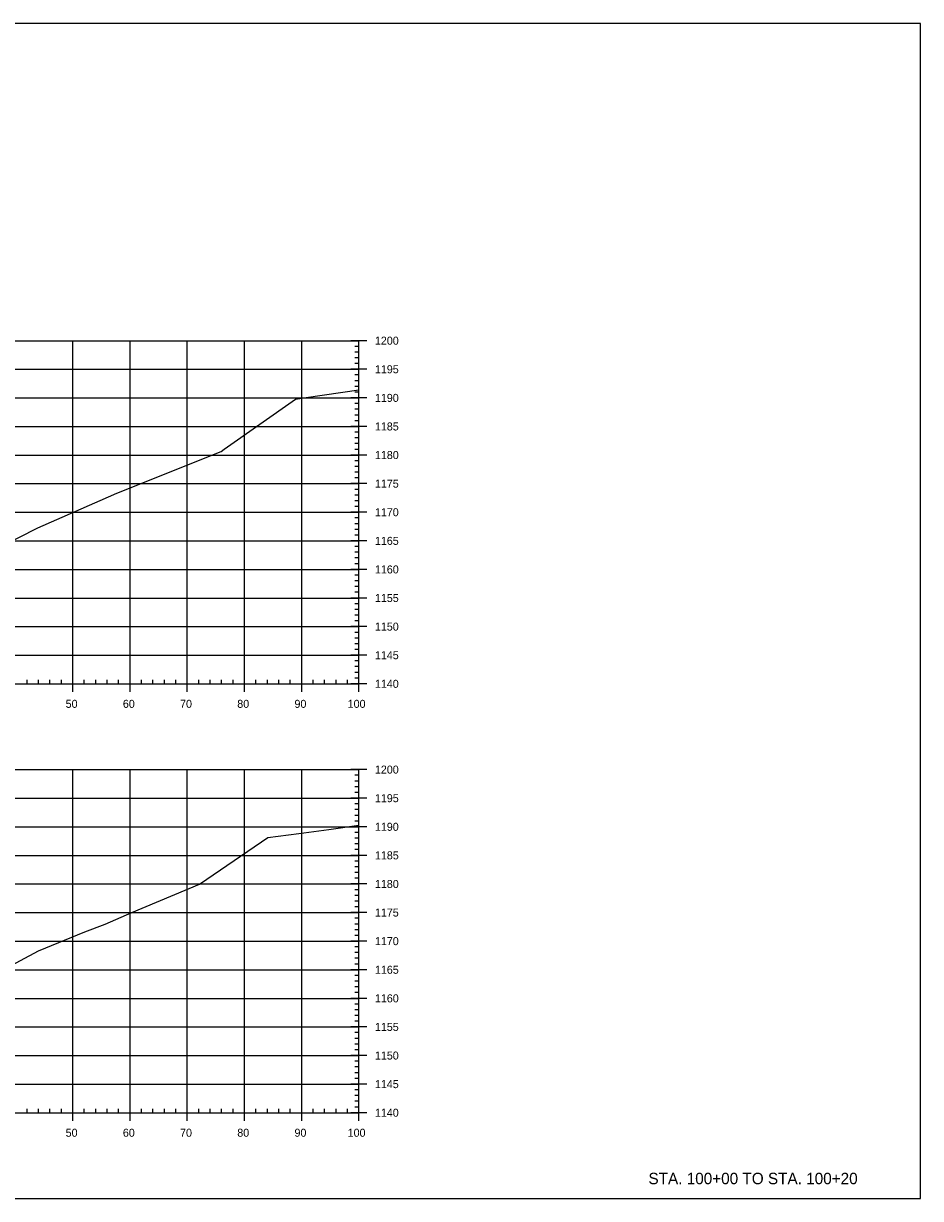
# Model space of a CAD drawing. Extents: x 688474 to 694748, y 765018 to 767373.
# Drawn here: x 689779.2 to 689936, y 765023.1 to 765228.6 of the extents above; entities that cross this region are included whole.
import ezdxf

# ---------------------------------------------------------------- set-up
doc = ezdxf.new("R2010")
doc.units = 0
for name, color, linetype in [('60', 7, 'Continuous'), ('R_Exist Surface', 7, 'Continuous'), ('R_Grid', 7, 'Continuous'), ('R_No Plot', 7, 'Continuous')]:
    doc.layers.add(name, color=color, linetype=linetype)

msp = doc.modelspace()

# ---------------------------------------------------------------- linework, layer by layer
at = {"layer": '60'}
for p, q in [((689839.22, 765173.14), (689836.42, 765173.14)), ((689837.82, 765172.14), (689837.12, 765172.14)), ((689837.82, 765113.14), (689837.82, 765173.14)), ((689837.82, 765171.14), (689837.12, 765171.14)), ((689837.82, 765170.14), (689837.12, 765170.14)), ((689839.22, 765168.14), (689836.42, 765168.14)), ((689837.82, 765169.14), (689837.12, 765169.14)), ((689837.82, 765167.14), (689837.12, 765167.14)), ((689837.82, 765166.14), (689837.12, 765166.14)), ((689837.82, 765165.14), (689837.12, 765165.14)), ((689837.82, 765164.14), (689837.12, 765164.14)), ((689839.22, 765163.14), (689836.42, 765163.14)), ((689837.82, 765162.14), (689837.12, 765162.14)), ((689837.82, 765161.14), (689837.12, 765161.14)), ((689837.82, 765160.14), (689837.12, 765160.14)), ((689839.22, 765158.14), (689836.42, 765158.14)), ((689837.82, 765159.14), (689837.12, 765159.14)), ((689837.82, 765157.14), (689837.12, 765157.14)), ((689837.82, 765156.14), (689837.12, 765156.14)), ((689837.82, 765155.14), (689837.12, 765155.14)), ((689837.82, 765154.14), (689837.12, 765154.14)), ((689839.22, 765153.14), (689836.42, 765153.14)), ((689837.82, 765152.14), (689837.12, 765152.14)), ((689837.82, 765151.14), (689837.12, 765151.14)), ((689837.82, 765150.14), (689837.12, 765150.14)), ((689839.22, 765148.14), (689836.42, 765148.14)), ((689837.82, 765149.14), (689837.12, 765149.14)), ((689837.82, 765147.14), (689837.12, 765147.14)), ((689837.82, 765146.14), (689837.12, 765146.14)), ((689837.82, 765145.14), (689837.12, 765145.14)), ((689837.82, 765144.14), (689837.12, 765144.14)), ((689839.22, 765143.14), (689836.42, 765143.14)), ((689837.82, 765142.14), (689837.12, 765142.14)), ((689837.82, 765141.14), (689837.12, 765141.14)), ((689837.82, 765140.14), (689837.12, 765140.14)), ((689839.22, 765138.14), (689836.42, 765138.14)), ((689837.82, 765139.14), (689837.12, 765139.14)), ((689837.82, 765137.14), (689837.12, 765137.14)), ((689837.82, 765136.14), (689837.12, 765136.14)), ((689837.82, 765135.14), (689837.12, 765135.14)), ((689839.22, 765133.14), (689836.42, 765133.14)), ((689837.82, 765134.14), (689837.12, 765134.14)), ((689837.82, 765132.14), (689837.12, 765132.14)), ((689837.82, 765131.14), (689837.12, 765131.14)), ((689837.82, 765130.14), (689837.12, 765130.14)), ((689837.82, 765129.14), (689837.12, 765129.14)), ((689839.22, 765128.14), (689836.42, 765128.14)), ((689837.82, 765127.14), (689837.12, 765127.14)), ((689837.82, 765126.14), (689837.12, 765126.14)), ((689837.82, 765125.14), (689837.12, 765125.14)), ((689839.22, 765123.14), (689836.42, 765123.14)), ((689837.82, 765124.14), (689837.12, 765124.14)), ((689837.82, 765122.14), (689837.12, 765122.14)), ((689837.82, 765121.14), (689837.12, 765121.14)), ((689837.82, 765120.14), (689837.12, 765120.14)), ((689837.82, 765119.14), (689837.12, 765119.14)), ((689839.22, 765118.14), (689836.42, 765118.14)), ((689837.82, 765117.14), (689837.12, 765117.14)), ((689837.82, 765116.14), (689837.12, 765116.14)), ((689837.82, 765115.14), (689837.12, 765115.14)), ((689637.82, 765113.14), (689837.82, 765113.14)), ((689779.82, 765113.14), (689779.82, 765113.84)), ((689781.82, 765113.14), (689781.82, 765113.84)), ((689783.82, 765113.14), (689783.82, 765113.84)), ((689785.82, 765113.14), (689785.82, 765113.84)), ((689787.82, 765111.74), (689787.82, 765114.54)), ((689789.82, 765113.14), (689789.82, 765113.84)), ((689791.82, 765113.14), (689791.82, 765113.84)), ((689793.82, 765113.14), (689793.82, 765113.84)), ((689795.82, 765113.14), (689795.82, 765113.84)), ((689797.82, 765111.74), (689797.82, 765114.54)), ((689799.82, 765113.14), (689799.82, 765113.84)), ((689801.82, 765113.14), (689801.82, 765113.84)), ((689803.82, 765113.14), (689803.82, 765113.84)), ((689805.82, 765113.14), (689805.82, 765113.84)), ((689807.82, 765111.74), (689807.82, 765114.54)), ((689809.82, 765113.14), (689809.82, 765113.84)), ((689811.82, 765113.14), (689811.82, 765113.84)), ((689813.82, 765113.14), (689813.82, 765113.84)), ((689815.82, 765113.14), (689815.82, 765113.84)), ((689817.82, 765111.74), (689817.82, 765114.54)), ((689819.82, 765113.14), (689819.82, 765113.84)), ((689821.82, 765113.14), (689821.82, 765113.84)), ((689823.82, 765113.14), (689823.82, 765113.84)), ((689825.82, 765113.14), (689825.82, 765113.84)), ((689827.82, 765111.74), (689827.82, 765114.54)), ((689829.82, 765113.14), (689829.82, 765113.84)), ((689831.82, 765113.14), (689831.82, 765113.84)), ((689833.82, 765113.14), (689833.82, 765113.84)), ((689835.82, 765113.14), (689835.82, 765113.84)), ((689839.22, 765113.14), (689836.42, 765113.14)), ((689837.82, 765114.14), (689837.12, 765114.14)), ((689837.82, 765111.74), (689837.82, 765114.54)), ((689839.22, 765098.14), (689836.42, 765098.14)), ((689837.82, 765038.14), (689837.82, 765098.14)), ((689837.82, 765097.14), (689837.12, 765097.14)), ((689837.82, 765096.14), (689837.12, 765096.14)), ((689837.82, 765095.14), (689837.12, 765095.14)), ((689837.82, 765094.14), (689837.12, 765094.14)), ((689839.22, 765093.14), (689836.42, 765093.14)), ((689837.82, 765092.14), (689837.12, 765092.14)), ((689837.82, 765091.14), (689837.12, 765091.14)), ((689837.82, 765090.14), (689837.12, 765090.14)), ((689839.22, 765088.14), (689836.42, 765088.14)), ((689837.82, 765089.14), (689837.12, 765089.14)), ((689837.82, 765087.14), (689837.12, 765087.14)), ((689837.82, 765086.14), (689837.12, 765086.14)), ((689837.82, 765085.14), (689837.12, 765085.14)), ((689837.82, 765084.14), (689837.12, 765084.14)), ((689839.22, 765083.14), (689836.42, 765083.14)), ((689837.82, 765082.14), (689837.12, 765082.14)), ((689837.82, 765081.14), (689837.12, 765081.14)), ((689837.82, 765080.14), (689837.12, 765080.14)), ((689839.22, 765078.14), (689836.42, 765078.14)), ((689837.82, 765079.14), (689837.12, 765079.14)), ((689837.82, 765077.14), (689837.12, 765077.14)), ((689837.82, 765076.14), (689837.12, 765076.14)), ((689837.82, 765075.14), (689837.12, 765075.14)), ((689837.82, 765074.14), (689837.12, 765074.14)), ((689839.22, 765073.14), (689836.42, 765073.14)), ((689837.82, 765072.14), (689837.12, 765072.14)), ((689837.82, 765071.14), (689837.12, 765071.14)), ((689837.82, 765070.14), (689837.12, 765070.14)), ((689839.22, 765068.14), (689836.42, 765068.14)), ((689837.82, 765069.14), (689837.12, 765069.14)), ((689837.82, 765067.14), (689837.12, 765067.14)), ((689837.82, 765066.14), (689837.12, 765066.14)), ((689837.82, 765065.14), (689837.12, 765065.14)), ((689837.82, 765064.14), (689837.12, 765064.14)), ((689839.22, 765063.14), (689836.42, 765063.14)), ((689837.82, 765062.14), (689837.12, 765062.14)), ((689837.82, 765061.14), (689837.12, 765061.14)), ((689837.82, 765060.14), (689837.12, 765060.14)), ((689837.82, 765059.14), (689837.12, 765059.14)), ((689839.22, 765058.14), (689836.42, 765058.14)), ((689837.82, 765057.14), (689837.12, 765057.14)), ((689837.82, 765056.14), (689837.12, 765056.14)), ((689837.82, 765055.14), (689837.12, 765055.14)), ((689839.22, 765053.14), (689836.42, 765053.14)), ((689837.82, 765054.14), (689837.12, 765054.14)), ((689837.82, 765052.14), (689837.12, 765052.14)), ((689837.82, 765051.14), (689837.12, 765051.14)), ((689837.82, 765050.14), (689837.12, 765050.14)), ((689837.82, 765049.14), (689837.12, 765049.14)), ((689839.22, 765048.14), (689836.42, 765048.14)), ((689837.82, 765047.14), (689837.12, 765047.14)), ((689837.82, 765046.14), (689837.12, 765046.14)), ((689837.82, 765045.14), (689837.12, 765045.14)), ((689839.22, 765043.14), (689836.42, 765043.14)), ((689837.82, 765044.14), (689837.12, 765044.14)), ((689837.82, 765042.14), (689837.12, 765042.14)), ((689837.82, 765041.14), (689837.12, 765041.14)), ((689779.82, 765038.14), (689779.82, 765038.84)), ((689781.82, 765038.14), (689781.82, 765038.84)), ((689783.82, 765038.14), (689783.82, 765038.84)), ((689785.82, 765038.14), (689785.82, 765038.84)), ((689787.82, 765036.74), (689787.82, 765039.54)), ((689789.82, 765038.14), (689789.82, 765038.84)), ((689791.82, 765038.14), (689791.82, 765038.84)), ((689793.82, 765038.14), (689793.82, 765038.84)), ((689795.82, 765038.14), (689795.82, 765038.84)), ((689797.82, 765036.74), (689797.82, 765039.54)), ((689799.82, 765038.14), (689799.82, 765038.84)), ((689801.82, 765038.14), (689801.82, 765038.84)), ((689803.82, 765038.14), (689803.82, 765038.84)), ((689805.82, 765038.14), (689805.82, 765038.84)), ((689807.82, 765036.74), (689807.82, 765039.54)), ((689809.82, 765038.14), (689809.82, 765038.84)), ((689811.82, 765038.14), (689811.82, 765038.84)), ((689813.82, 765038.14), (689813.82, 765038.84)), ((689815.82, 765038.14), (689815.82, 765038.84)), ((689817.82, 765036.74), (689817.82, 765039.54)), ((689819.82, 765038.14), (689819.82, 765038.84)), ((689821.82, 765038.14), (689821.82, 765038.84)), ((689823.82, 765038.14), (689823.82, 765038.84)), ((689825.82, 765038.14), (689825.82, 765038.84)), ((689827.82, 765036.74), (689827.82, 765039.54)), ((689829.82, 765038.14), (689829.82, 765038.84)), ((689831.82, 765038.14), (689831.82, 765038.84)), ((689833.82, 765038.14), (689833.82, 765038.84)), ((689835.82, 765038.14), (689835.82, 765038.84)), ((689837.82, 765040.14), (689837.12, 765040.14)), ((689837.82, 765039.14), (689837.12, 765039.14)), ((689837.82, 765036.74), (689837.82, 765039.54)), ((689637.82, 765038.14), (689837.82, 765038.14)), ((689839.22, 765038.14), (689836.42, 765038.14))]:
    msp.add_line(p, q, dxfattribs=at)
at = {"layer": 'R_Exist Surface'}
for points in [[(689768.38, 765133.66), (689781.67, 765140.44), (689794.96, 765146.23), (689795.07, 765146.28), (689795.22, 765146.34), (689813.74, 765153.79), (689814.26, 765154.15), (689826.74, 765162.93), (689828.59, 765163.2), (689837.82, 765164.57)], [(689776.29, 765063.47), (689781.8, 765066.47), (689789.89, 765069.77), (689793.49, 765071.12), (689798.13, 765073.16), (689809.94, 765078.11), (689813.63, 765080.59), (689821.88, 765086.27), (689827.31, 765086.99), (689832.58, 765087.69), (689837.82, 765088.42)]]:
    msp.add_lwpolyline(points, dxfattribs=at)
at = {"layer": 'R_Grid'}
for p, q in [((689637.82, 765173.14), (689837.82, 765173.14)), ((689787.82, 765113.14), (689787.82, 765173.14)), ((689797.82, 765113.14), (689797.82, 765173.14)), ((689807.82, 765113.14), (689807.82, 765173.14)), ((689817.82, 765113.14), (689817.82, 765173.14)), ((689827.82, 765113.14), (689827.82, 765173.14)), ((689837.82, 765113.14), (689837.82, 765173.14)), ((689637.82, 765168.14), (689837.82, 765168.14)), ((689637.82, 765163.14), (689837.82, 765163.14)), ((689637.82, 765158.14), (689837.82, 765158.14)), ((689637.82, 765153.14), (689837.82, 765153.14)), ((689637.82, 765148.14), (689837.82, 765148.14)), ((689637.82, 765143.14), (689837.82, 765143.14)), ((689637.82, 765138.14), (689837.82, 765138.14)), ((689637.82, 765133.14), (689837.82, 765133.14)), ((689637.82, 765128.14), (689837.82, 765128.14)), ((689637.82, 765123.14), (689837.82, 765123.14)), ((689637.82, 765118.14), (689837.82, 765118.14)), ((689637.82, 765113.14), (689837.82, 765113.14)), ((689637.82, 765098.14), (689837.82, 765098.14)), ((689787.82, 765038.14), (689787.82, 765098.14)), ((689797.82, 765038.14), (689797.82, 765098.14)), ((689807.82, 765038.14), (689807.82, 765098.14)), ((689817.82, 765038.14), (689817.82, 765098.14)), ((689827.82, 765038.14), (689827.82, 765098.14)), ((689837.82, 765038.14), (689837.82, 765098.14)), ((689637.82, 765093.14), (689837.82, 765093.14)), ((689637.82, 765088.14), (689837.82, 765088.14)), ((689637.82, 765083.14), (689837.82, 765083.14)), ((689637.82, 765078.14), (689837.82, 765078.14)), ((689637.82, 765073.14), (689837.82, 765073.14)), ((689637.82, 765068.14), (689837.82, 765068.14)), ((689637.82, 765063.14), (689837.82, 765063.14)), ((689637.82, 765058.14), (689837.82, 765058.14)), ((689637.82, 765053.14), (689837.82, 765053.14)), ((689637.82, 765048.14), (689837.82, 765048.14)), ((689637.82, 765043.14), (689837.82, 765043.14)), ((689637.82, 765038.14), (689837.82, 765038.14))]:
    msp.add_line(p, q, dxfattribs=at)
at = {"layer": 'R_No Plot'}
msp.add_lwpolyline([(689619.82, 765023.14), (689936, 765023.14), (689936, 765228.6), (689619.82, 765228.6)], close=True, dxfattribs=at)

# ---------------------------------------------------------------- texts
at = {"layer": '60'}
for s, height, p in [('1200', 1.4, (689840.62, 765172.44)), ('1195', 1.4, (689840.62, 765167.44)), ('1190', 1.4, (689840.62, 765162.44)), ('1185', 1.4, (689840.62, 765157.44)), ('1180', 1.4, (689840.62, 765152.44)), ('1175', 1.4, (689840.62, 765147.44)), ('1170', 1.4, (689840.62, 765142.44)), ('1165', 1.4, (689840.62, 765137.44)), ('1160', 1.4, (689840.62, 765132.44)), ('1155', 1.4, (689840.62, 765127.44)), ('1150', 1.4, (689840.62, 765122.44)), ('1145', 1.4, (689840.62, 765117.44)), ('1140', 1.4, (689840.62, 765112.44)), ('50', 1.4, (689786.56, 765108.94)), ('60', 1.4, (689796.56, 765108.94)), ('70', 1.4, (689806.56, 765108.94)), ('80', 1.4, (689816.56, 765108.94)), ('90', 1.4, (689826.56, 765108.94)), ('100', 1.4, (689835.86, 765108.94)), ('1200', 1.4, (689840.62, 765097.44)), ('1195', 1.4, (689840.62, 765092.44)), ('1190', 1.4, (689840.62, 765087.44)), ('1185', 1.4, (689840.62, 765082.44)), ('1180', 1.4, (689840.62, 765077.44)), ('1175', 1.4, (689840.62, 765072.44)), ('1170', 1.4, (689840.62, 765067.44)), ('1165', 1.4, (689840.62, 765062.44)), ('1160', 1.4, (689840.62, 765057.44)), ('1155', 1.4, (689840.62, 765052.44)), ('1150', 1.4, (689840.62, 765047.44)), ('1145', 1.4, (689840.62, 765042.44)), ('1140', 1.4, (689840.62, 765037.44)), ('50', 1.4, (689786.56, 765033.94)), ('60', 1.4, (689796.56, 765033.94)), ('70', 1.4, (689806.56, 765033.94)), ('80', 1.4, (689816.56, 765033.94)), ('90', 1.4, (689826.56, 765033.94)), ('100', 1.4, (689835.86, 765033.94)), ('STA. 100+00 TO STA. 100+20', 2, (689888.44, 765025.64))]:
    msp.add_text(s, height=height, dxfattribs=at).set_placement(p)

doc.saveas('drawing.dxf')
